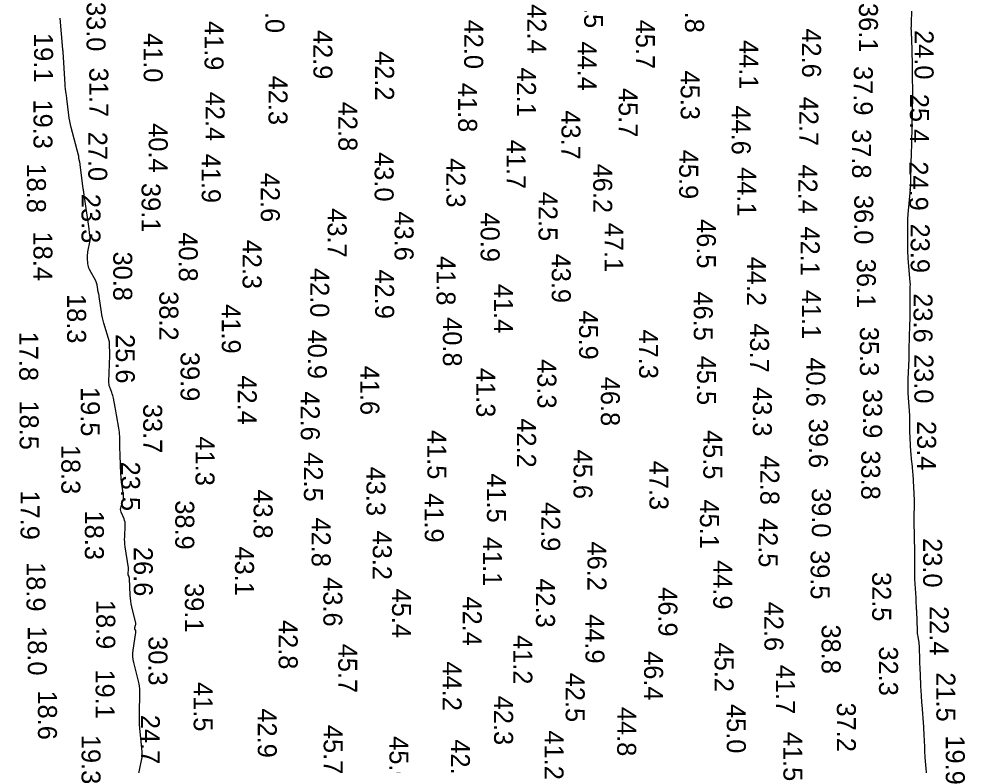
# Model space of a CAD drawing. Extents: x 1178573 to 1187098, y 693282 to 751751.
# Drawn here: x 1180974 to 1181597, y 699291 to 699783 of the extents above; entities that cross this region are included whole.
import ezdxf

# ---------------------------------------------------------------- set-up
doc = ezdxf.new("R2010")
doc.units = 0
doc.layers.add('V-HYDS-MAJR', color=7, linetype='Continuous')
doc.layers.add('V-HYDS-SOUN', color=7, linetype='Continuous')

msp = doc.modelspace()

# ---------------------------------------------------------------- linework, layer by layer
at = {"layer": 'V-HYDS-MAJR'}
for points in [[(1181561.86, 699790.61), (1181561.56, 699777.57), (1181561.55, 699776.92), (1181561.55, 699776.27), (1181561.57, 699775.62), (1181561.59, 699774.97), (1181561.72, 699772.37), (1181561.75, 699771.72), (1181561.78, 699771.06), (1181561.8, 699770.41), (1181561.82, 699769.76), (1181562.31, 699753.04), (1181562.32, 699752.78), (1181562.32, 699752.52), (1181562.33, 699752.26), (1181562.33, 699751.99), (1181562.34, 699750.94), (1181562.34, 699750.68), (1181562.34, 699750.42), (1181562.34, 699750.15), (1181562.34, 699749.89), (1181562.5, 699730.17), (1181562.5, 699730.13), (1181562.5, 699730.09), (1181562.5, 699730.05), (1181562.5, 699730), (1181562.5, 699729.84), (1181562.5, 699729.8), (1181562.5, 699729.76), (1181562.5, 699729.71), (1181562.5, 699729.67), (1181562.45, 699727.16), (1181562.44, 699726.73), (1181562.43, 699726.3), (1181562.42, 699725.86), (1181562.41, 699725.43), (1181562, 699707.91), (1181561.93, 699704.84), (1181561.86, 699701.77), (1181561.79, 699698.71), (1181561.72, 699695.64), (1181561.29, 699677.08), (1181561.28, 699676.36), (1181561.26, 699675.64), (1181561.24, 699674.92), (1181561.21, 699674.19), (1181561.08, 699670.11), (1181561.07, 699670.01), (1181561.07, 699669.98), (1181561.06, 699670.01), (1181561.05, 699670.11), (1181561.01, 699670.61), (1181561, 699670.71), (1181560.99, 699670.74), (1181560.98, 699670.71), (1181560.97, 699670.61), (1181559.43, 699654.06), (1181559.41, 699653.8), (1181559.39, 699653.55), (1181559.38, 699653.29), (1181559.37, 699653.04), (1181559.36, 699652.02), (1181559.36, 699651.77), (1181559.36, 699651.51), (1181559.36, 699651.26), (1181559.36, 699651.01), (1181559.21, 699630.2), (1181559.22, 699629.78), (1181559.23, 699629.36), (1181559.25, 699628.94), (1181559.28, 699628.52), (1181559.41, 699626.84), (1181559.44, 699626.42), (1181559.48, 699626.01), (1181559.51, 699625.59), (1181559.55, 699625.17), (1181560.88, 699609.2), (1181560.9, 699608.87), (1181560.92, 699608.55), (1181560.92, 699608.23), (1181560.92, 699607.91), (1181560.9, 699606.61), (1181560.9, 699606.29), (1181560.89, 699605.97), (1181560.89, 699605.64), (1181560.89, 699605.32), (1181560.77, 699587.56), (1181560.77, 699587.03), (1181560.76, 699586.49), (1181560.75, 699585.96), (1181560.74, 699585.43), (1181560.69, 699583.29), (1181560.68, 699582.76), (1181560.67, 699582.22), (1181560.65, 699581.69), (1181560.64, 699581.16), (1181560.24, 699565.22), (1181560.23, 699564.67), (1181560.22, 699564.11), (1181560.2, 699563.56), (1181560.18, 699563.01), (1181560.11, 699560.81), (1181560.09, 699560.26), (1181560.07, 699559.71), (1181560.05, 699559.16), (1181560.03, 699558.61), (1181559.57, 699545.63), (1181559.55, 699544.85), (1181559.52, 699544.08), (1181559.5, 699543.31), (1181559.48, 699542.54), (1181559.41, 699539.45), (1181559.41, 699538.67), (1181559.42, 699537.9), (1181559.44, 699537.13), (1181559.49, 699536.36), (1181560.57, 699521.53), (1181560.62, 699520.67), (1181560.65, 699519.82), (1181560.66, 699518.96), (1181560.65, 699518.1), (1181560.55, 699514.67), (1181560.54, 699513.81), (1181560.54, 699512.95), (1181560.56, 699512.1), (1181560.6, 699511.24), (1181561.33, 699497.69), (1181561.41, 699496.46), (1181561.5, 699495.24), (1181561.61, 699494.01), (1181561.74, 699492.78), (1181562.28, 699487.89), (1181562.41, 699486.66), (1181562.52, 699485.43), (1181562.61, 699484.21), (1181562.69, 699482.98), (1181563.63, 699465.85), (1181563.68, 699464.7), (1181563.7, 699463.56), (1181563.7, 699462.41), (1181563.67, 699461.26), (1181563.52, 699456.67), (1181563.49, 699455.52), (1181563.47, 699454.38), (1181563.47, 699453.23), (1181563.48, 699452.08), (1181563.83, 699431.66), (1181563.85, 699430.18), (1181563.86, 699428.7), (1181563.86, 699427.22), (1181563.85, 699425.74), (1181563.78, 699419.82), (1181563.77, 699418.34), (1181563.8, 699416.86), (1181563.85, 699415.38), (1181563.92, 699413.9), (1181564.67, 699401.6), (1181564.71, 699400.85), (1181564.76, 699400.11), (1181564.8, 699399.36), (1181564.84, 699398.61), (1181565, 699395.61), (1181565.04, 699394.86), (1181565.07, 699394.12), (1181565.11, 699393.37), (1181565.13, 699392.62), (1181565.59, 699379.92), (1181565.64, 699378.92), (1181565.73, 699377.92), (1181565.84, 699376.93), (1181565.99, 699375.94), (1181566.66, 699371.98), (1181566.8, 699370.99), (1181566.91, 699369.99), (1181566.98, 699368.99), (1181567.02, 699367.99), (1181567.12, 699361.74), (1181567.14, 699360.36), (1181567.18, 699358.98), (1181567.22, 699357.61), (1181567.28, 699356.23), (1181567.56, 699349.51), (1181567.63, 699347.97), (1181567.71, 699346.42), (1181567.79, 699344.88), (1181567.88, 699343.34), (1181568.25, 699337.16), (1181568.35, 699335.62), (1181568.45, 699334.08), (1181568.55, 699332.54), (1181568.66, 699330.99), (1181569.69, 699316.55), (1181569.77, 699315.39), (1181569.85, 699314.22), (1181569.92, 699313.06), (1181569.98, 699311.89), (1181570.27, 699306.6), (1181570.31, 699305.75), (1181570.35, 699304.89), (1181570.38, 699304.04), (1181570.41, 699303.18), (1181570.52, 699299.76), (1181570.55, 699298.91), (1181570.6, 699298.05), (1181570.65, 699297.2), (1181570.72, 699296.35), (1181572.18, 699279.3)], [(1181051.93, 699280.61), (1181055.03, 699295.48), (1181055.08, 699295.69), (1181055.11, 699295.91), (1181055.15, 699296.13), (1181055.17, 699296.35), (1181055.26, 699297.23), (1181055.28, 699297.45), (1181055.3, 699297.67), (1181055.3, 699297.9), (1181055.31, 699298.12), (1181055.3, 699299.1), (1181055.29, 699299.34), (1181055.28, 699299.58), (1181055.27, 699299.82), (1181055.25, 699300.05), (1181053.77, 699315.67), (1181053.58, 699318.03), (1181053.45, 699320.39), (1181053.39, 699322.76), (1181053.4, 699325.12), (1181053.63, 699338.88), (1181053.64, 699339.11), (1181053.64, 699339.34), (1181053.64, 699339.57), (1181053.64, 699339.8), (1181053.64, 699340.72), (1181053.64, 699340.95), (1181053.63, 699341.18), (1181053.61, 699341.41), (1181053.59, 699341.64), (1181053.41, 699343.38), (1181053.37, 699343.75), (1181053.31, 699344.11), (1181053.24, 699344.48), (1181053.16, 699344.84), (1181049.77, 699358.87), (1181049.38, 699360.89), (1181049.19, 699362.93), (1181049.19, 699364.97), (1181049.4, 699367.02), (1181051.12, 699378.78), (1181051.14, 699379.07), (1181051.13, 699379.35), (1181051.07, 699379.63), (1181050.97, 699379.9), (1181050.48, 699380.98), (1181050.39, 699381.25), (1181050.35, 699381.53), (1181050.36, 699381.8), (1181050.43, 699382.08), (1181050.93, 699383.53), (1181051.02, 699383.86), (1181051.06, 699384.2), (1181051.05, 699384.54), (1181051, 699384.88), (1181048.45, 699395.55), (1181048.04, 699397.45), (1181047.73, 699399.36), (1181047.5, 699401.29), (1181047.36, 699403.23), (1181046.85, 699414.32), (1181046.82, 699414.63), (1181046.77, 699414.93), (1181046.69, 699415.23), (1181046.58, 699415.53), (1181046.1, 699416.69), (1181046, 699416.99), (1181045.94, 699417.28), (1181045.92, 699417.59), (1181045.95, 699417.9), (1181046.19, 699419.64), (1181046.23, 699420.03), (1181046.24, 699420.42), (1181046.23, 699420.82), (1181046.18, 699421.21), (1181044.04, 699435.19), (1181043.83, 699436.79), (1181043.71, 699438.4), (1181043.67, 699440.01), (1181043.71, 699441.62), (1181044.07, 699449.04), (1181044.07, 699450.17), (1181043.94, 699451.28), (1181043.69, 699452.37), (1181043.32, 699453.43), (1181041.43, 699458.01), (1181041.15, 699458.89), (1181041.04, 699459.78), (1181041.1, 699460.67), (1181041.32, 699461.57), (1181042.56, 699465.16), (1181042.81, 699466.07), (1181042.95, 699466.98), (1181042.99, 699467.91), (1181042.91, 699468.85), (1181041.84, 699476.49), (1181041.64, 699478.07), (1181041.48, 699479.67), (1181041.35, 699481.26), (1181041.27, 699482.86), (1181040.74, 699495.46), (1181040.72, 699495.9), (1181040.7, 699496.34), (1181040.67, 699496.79), (1181040.65, 699497.23), (1181040.54, 699499), (1181040.51, 699499.44), (1181040.5, 699499.88), (1181040.48, 699500.33), (1181040.48, 699500.77), (1181040.43, 699507.95), (1181040.39, 699509.29), (1181040.29, 699510.62), (1181040.14, 699511.95), (1181039.92, 699513.27), (1181038.31, 699521.97), (1181038.07, 699523.26), (1181037.83, 699524.55), (1181037.59, 699525.84), (1181037.35, 699527.13), (1181036.28, 699532.98), (1181036.08, 699533.92), (1181035.85, 699534.85), (1181035.57, 699535.77), (1181035.25, 699536.68), (1181033.89, 699540.3), (1181033.6, 699541.21), (1181033.4, 699542.13), (1181033.3, 699543.07), (1181033.29, 699544.03), (1181033.96, 699561.09), (1181033.97, 699561.73), (1181033.98, 699562.37), (1181033.96, 699563), (1181033.93, 699563.64), (1181033.73, 699566.94), (1181033.72, 699567.21), (1181033.71, 699567.47), (1181033.71, 699567.74), (1181033.72, 699568), (1181033.77, 699569.07), (1181033.77, 699569.33), (1181033.75, 699569.59), (1181033.71, 699569.85), (1181033.64, 699570.11), (1181030.07, 699582.29), (1181029.57, 699584.1), (1181029.15, 699585.92), (1181028.78, 699587.76), (1181028.49, 699589.62), (1181027.01, 699600.02), (1181026.95, 699600.4), (1181026.88, 699600.78), (1181026.8, 699601.15), (1181026.71, 699601.52), (1181026.31, 699602.99), (1181026.22, 699603.36), (1181026.14, 699603.73), (1181026.07, 699604.11), (1181026, 699604.48), (1181025.51, 699607.68), (1181025.39, 699608.34), (1181025.21, 699608.97), (1181024.97, 699609.58), (1181024.68, 699610.18), (1181020.6, 699617.81), (1181020.18, 699618.7), (1181019.87, 699619.61), (1181019.65, 699620.56), (1181019.54, 699621.53), (1181019.29, 699625.48), (1181019.26, 699626.46), (1181019.29, 699627.44), (1181019.38, 699628.42), (1181019.53, 699629.39), (1181020.95, 699636.83), (1181021.03, 699637.37), (1181021.06, 699637.92), (1181021.05, 699638.46), (1181021, 699639.01), (1181020.59, 699641.86), (1181020.56, 699642.08), (1181020.53, 699642.3), (1181020.5, 699642.53), (1181020.48, 699642.75), (1181020.39, 699643.64), (1181020.36, 699643.86), (1181020.34, 699644.08), (1181020.31, 699644.3), (1181020.28, 699644.52), (1181016.81, 699668.52), (1181016.78, 699668.74), (1181016.75, 699668.96), (1181016.71, 699669.18), (1181016.68, 699669.39), (1181016.55, 699670.27), (1181016.52, 699670.49), (1181016.48, 699670.71), (1181016.46, 699670.93), (1181016.43, 699671.15), (1181014.49, 699686.65), (1181014.43, 699687.09), (1181014.35, 699687.54), (1181014.26, 699687.98), (1181014.16, 699688.41), (1181013.52, 699690.87), (1181013.5, 699690.95), (1181013.48, 699691.02), (1181013.47, 699691.1), (1181013.46, 699691.17), (1181013.43, 699691.48), (1181013.42, 699691.55), (1181013.42, 699691.63), (1181013.42, 699691.7), (1181013.42, 699691.78), (1181013.42, 699692.42), (1181013.42, 699692.55), (1181013.41, 699692.68), (1181013.39, 699692.81), (1181013.36, 699692.94), (1181008.49, 699711.3), (1181007.99, 699713.31), (1181007.57, 699715.34), (1181007.22, 699717.38), (1181006.93, 699719.44), (1181005.64, 699730.25), (1181005.54, 699731.03), (1181005.44, 699731.8), (1181005.33, 699732.57), (1181005.22, 699733.34), (1181004.76, 699736.42), (1181004.65, 699737.19), (1181004.56, 699737.96), (1181004.49, 699738.74), (1181004.44, 699739.51), (1181003.2, 699761.11), (1181003.19, 699761.22), (1181003.18, 699761.34), (1181003.17, 699761.46), (1181003.16, 699761.58), (1181003.08, 699762.22), (1181003.08, 699762.25), (1181003.08, 699762.28), (1181003.07, 699762.31), (1181003.07, 699762.35), (1181003.06, 699762.48), (1181003.05, 699762.51), (1181003.05, 699762.54), (1181003.05, 699762.57), (1181003.04, 699762.61), (1181001.34, 699783.29)]]:
    msp.add_lwpolyline(points, dxfattribs=at)

# ---------------------------------------------------------------- texts
at = {"layer": 'V-HYDS-SOUN'}
for s, p in [('44.5 ', (1181346.33, 699809.15)), ('43.0 ', (1181136.41, 699805.97)), ('45.8 ', (1181412.77, 699806.12)), ('33.0 ', (1181018.63, 699793.9)), ('42.4 ', (1181308.92, 699792.42)), ('36.1 ', (1181527.3, 699793.22)), ('41.9 ', (1181096.33, 699781.39)), ('42.0 ', (1181267.32, 699782.28)), ('45.7 ', (1181380.38, 699782.24)), ('19.1 ', (1180984.06, 699773.44)), ('41.0 ', (1181056.23, 699773.46)), ('42.9 ', (1181168.02, 699775.48)), ('42.6 ', (1181489.82, 699776.5)), ('24.0 ', (1181563.94, 699775.36)), ('44.4 ', (1181342.02, 699767.94)), ('44.1 ', (1181448.56, 699768.85)), ('42.2 ', (1181208.65, 699761.5)), ('31.7 ', (1181020.43, 699750.64)), ('42.1 ', (1181302.07, 699750.74)), ('45.3 ', (1181409.9, 699748.74)), ('37.9 ', (1181523.89, 699751.69)), ('42.3 ', (1181138.45, 699745.4)), ('41.8 ', (1181263.32, 699740.61)), ('42.4 ', (1181097.01, 699734.78)), ('45.7 ', (1181369.06, 699737.29)), ('19.3 ', (1180983.66, 699729.68)), ('42.8 ', (1181184.45, 699728.17)), ('42.7 ', (1181488.08, 699731.55)), ('25.4 ', (1181560.85, 699733.43)), ('43.7 ', (1181331.39, 699722.53)), ('44.6 ', (1181443.47, 699725.78)), ('40.4 ', (1181059.54, 699714.04)), ('37.8 ', (1181522.81, 699710.13)), ('27.0 ', (1181019.75, 699708.46)), ('41.7 ', (1181295.34, 699703.24)), ('45.9 ', (1181408.9, 699696.58)), ('41.9 ', (1181094.46, 699694.02)), ('43.0 ', (1181208.33, 699694.98)), ('42.3 ', (1181255.6, 699691.03)), ('18.8 ', (1180979.34, 699687.55)), ('46.2 ', (1181352.28, 699687.42)), ('44.1 ', (1181447.15, 699685.12)), ('42.4 ', (1181487.36, 699686.88)), ('24.9 ', (1181560.37, 699688.93)), ('42.6 ', (1181133.36, 699681.39)), ('39.1 ', (1181054.86, 699674.69)), ('23.3 ', (1181015.28, 699667.51)), ('42.5 ', (1181316.28, 699668.9)), ('36.0 ', (1181524.21, 699666.8)), ('43.7 ', (1181177.39, 699658.06)), ('43.6 ', (1181221.48, 699655.96)), ('40.9 ', (1181278.15, 699655.21)), ('47.1 ', (1181359.72, 699648.5)), ('46.5 ', (1181420.54, 699650.92)), ('23.9 ', (1181561.36, 699647.95)), ('18.4 ', (1180983.62, 699642.72)), ('40.8 ', (1181079.34, 699642.21)), ('42.1 ', (1181488.92, 699646.04)), ('42.3 ', (1181121.39, 699637.39)), ('30.8 ', (1181036.19, 699629.55)), ('43.9 ', (1181324.97, 699628.17)), ('41.8 ', (1181249.09, 699626.6)), ('44.2 ', (1181453.56, 699626.2)), ('36.1 ', (1181525.89, 699624.78)), ('42.0 ', (1181165.94, 699618.7)), ('42.9 ', (1181208.67, 699617.71)), ('38.2 ', (1181066.55, 699603.43)), ('41.4 ', (1181286.94, 699608.27)), ('46.5 ', (1181418.51, 699603.28)), ('41.1 ', (1181489.74, 699604.38)), ('18.3 ', (1181005.8, 699601.6)), ('23.6 ', (1181563.25, 699602.06)), ('41.9 ', (1181107.68, 699594.84)), ('45.9 ', (1181342.98, 699590.83)), ('40.8 ', (1181253.29, 699586.31)), ('40.9 ', (1181164.34, 699578.14)), ('47.3 ', (1181382.51, 699578.2)), ('43.7 ', (1181455.57, 699582.27)), ('35.3 ', (1181527.91, 699579.98)), ('17.8 ', (1180974.25, 699576.83)), ('25.6 ', (1181037.86, 699575.19)), ('39.9 ', (1181080.55, 699563.44)), ('45.5 ', (1181420.67, 699560.96)), ('40.6 ', (1181492.61, 699559.9)), ('23.0 ', (1181563.77, 699562.04)), ('41.6 ', (1181198.94, 699554.42)), ('41.3 ', (1181275.29, 699552.91)), ('43.3 ', (1181315.51, 699558.68)), ('42.4 ', (1181118.2, 699548)), ('46.8 ', (1181357.32, 699547.1)), ('43.3 ', (1181457.41, 699540.31)), ('19.5 ', (1181014.83, 699540.36)), ('42.6 ', (1181159.67, 699537.52)), ('33.9 ', (1181530.02, 699539.1)), ('18.5 ', (1180974.55, 699531.46)), ('33.7 ', (1181055.93, 699529.22)), ('42.2 ', (1181302.15, 699519.74)), ('39.6 ', (1181494.35, 699519.48)), ('23.4 ', (1181565.61, 699517.98)), ('41.5 ', (1181243.08, 699512.08)), ('45.5 ', (1181424.81, 699512.04)), ('41.3 ', (1181090.38, 699507.8)), ('18.3 ', (1181002, 699502.25)), ('42.5 ', (1181161.75, 699497.38)), ('45.6 ', (1181339.3, 699499.14)), ('33.8 ', (1181528.81, 699498.61)), ('23.5 ', (1181041.34, 699491.21)), ('47.3 ', (1181389.33, 699491.85)), ('42.8 ', (1181462.34, 699495.23)), ('43.3 ', (1181202.95, 699487.92)), ('41.5 ', (1181282.32, 699483.53)), ('43.8 ', (1181128.65, 699472.96)), ('39.0 ', (1181496.29, 699473.75)), ('17.9 ', (1180975.14, 699472.23)), ('38.9 ', (1181077.04, 699465.74)), ('41.9 ', (1181241.34, 699470.4)), ('45.1 ', (1181422.58, 699466.32)), ('42.9 ', (1181318.05, 699464.65)), ('18.3 ', (1181017.51, 699458.98)), ('42.8 ', (1181166.87, 699454.39)), ('42.5 ', (1181461.26, 699454.1)), ('43.2 ', (1181207.1, 699445.82)), ('41.1 ', (1181279.76, 699441.65)), ('26.6 ', (1181049.73, 699435.03)), ('43.1 ', (1181116.38, 699435.35)), ('46.2 ', (1181348.51, 699438.6)), ('23.0 ', (1181569.55, 699440.81)), ('39.5 ', (1181495.48, 699432.91)), ('18.9 ', (1180979.07, 699425.02)), ('44.9 ', (1181431.34, 699426.37)), ('32.5 ', (1181536.03, 699418.54)), ('39.1 ', (1181083.34, 699411.2)), ('43.6 ', (1181174.57, 699415.08)), ('42.3 ', (1181314.59, 699414.36)), ('45.4 ', (1181219.81, 699407.61)), ('46.9 ', (1181395.21, 699408.52)), ('18.9 ', (1181025.01, 699400.19)), ('42.4 ', (1181266.4, 699402.39)), ('42.6 ', (1181465.02, 699398.97)), ('44.9 ', (1181347.18, 699390.74)), ('22.4 ', (1181573.88, 699396.09)), ('42.8 ', (1181145.15, 699386.93)), ('18.0 ', (1180979.92, 699382.87)), ('38.8 ', (1181502.73, 699383.95)), ('30.3 ', (1181059.38, 699376.24)), ('41.2 ', (1181299.69, 699377.02)), ('45.2 ', (1181432.23, 699372.07)), ('45.7 ', (1181184.35, 699371.31)), ('46.4 ', (1181385.79, 699366.4)), ('32.3 ', (1181540.51, 699369.51)), ('44.2 ', (1181253.1, 699359.6)), ('19.1 ', (1181024.58, 699354.34)), ('41.7 ', (1181472.63, 699357.47)), ('42.5 ', (1181334.16, 699352.2)), ('21.5 ', (1181578.28, 699352.5)), ('41.5 ', (1181089.15, 699346.06)), ('18.6 ', (1180986.61, 699340.51)), ('42.3 ', (1181287, 699337.06)), ('42.9 ', (1181131.37, 699328.7)), ('44.8 ', (1181368.08, 699329.68)), ('45.0 ', (1181440.25, 699331.63)), ('37.2 ', (1181512.75, 699332.57)), ('24.7 ', (1181054.36, 699324.46)), ('45.7 ', (1181174.77, 699317.84)), ('19.3 ', (1181015.32, 699311.28)), ('45.6 ', (1181218.11, 699310.42)), ('41.2 ', (1181320.23, 699314.19)), ('41.5 ', (1181477.53, 699313.26)), ('19.9 ', (1181584.49, 699310.95)), ('42.9 ', (1181258.57, 699308.36))]:
    msp.add_text(s, height=12.5, rotation=270, dxfattribs=at).set_placement(p)

doc.saveas('drawing.dxf')
